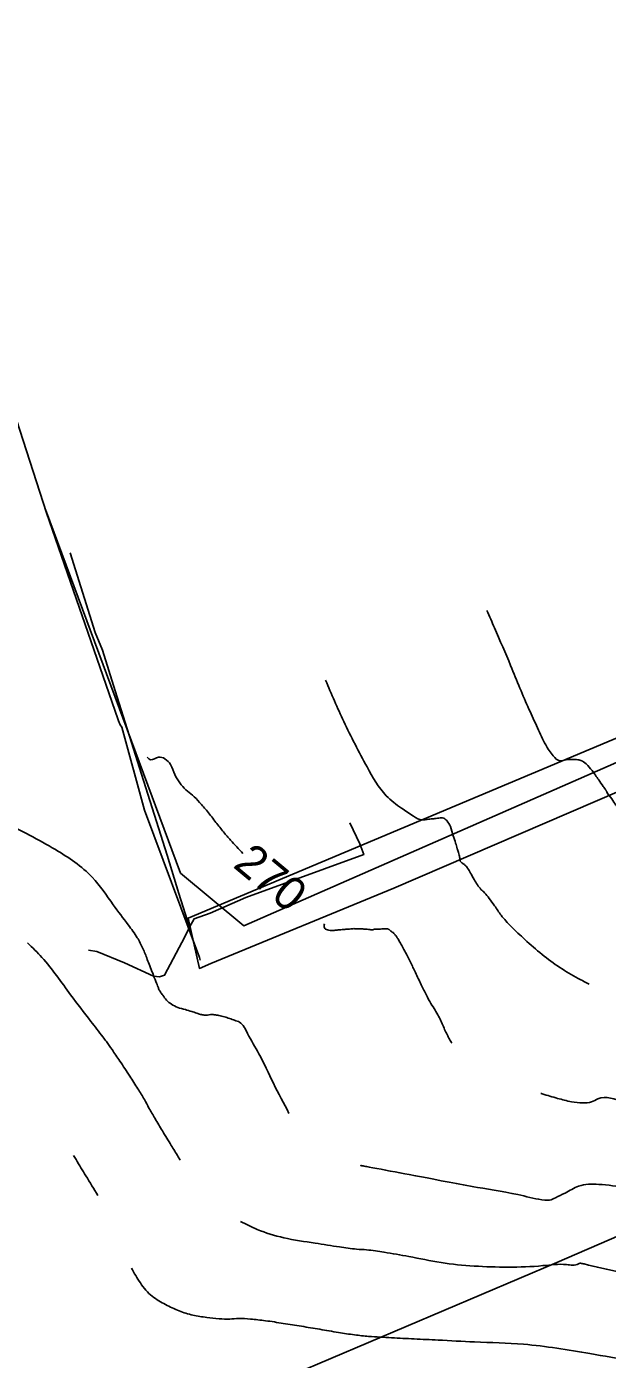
# Model space of a CAD drawing. Extents: x -478464 to -472469, y -1120963 to -1113785.
# Drawn here: x -475785 to -475715, y -1117032.4 to -1116871.8 of the extents above; entities that cross this region are included whole.
import ezdxf

# ---------------------------------------------------------------- set-up
doc = ezdxf.new("R2010")
doc.units = 0
for name, color, linetype in [('ObPÚ', 7, 'Continuous'), ('telekomunikační kabel_O2', 7, 'Continuous'), ('VAK_vodovod', 7, 'Continuous'), ('Vrstevnice_hlavni', 7, 'Continuous'), ('Vrstevnice_popis', 7, 'Continuous'), ('Vrstevnice_vedlejsi', 7, 'Continuous')]:
    doc.layers.add(name, color=color, linetype=linetype)

msp = doc.modelspace()

# ---------------------------------------------------------------- linework, layer by layer
at = {"layer": 'ObPÚ'}
msp.add_lwpolyline([(-475582.38, -1116858.98), (-475609.93, -1116877.62), (-475644, -1116900.2), (-475634.09, -1116923.52), (-475698.19, -1116950.87), (-475765.52, -1116979.2), (-475764.15, -1116985.27), (-475762.77, -1116984.68), (-475740.75, -1116975.6), (-475704.37, -1116959.91), (-475684.75, -1117004.96), (-475721.12, -1117020.7), (-475752.88, -1117034.21), (-475749.21, -1117050.03), (-475744.47, -1117062.49), (-475748.91, -1117064.2), (-475744.85, -1117076.56), (-475754.59, -1117081.64), (-475740.69, -1117110.42), (-475761.49, -1117122.43), (-475769.31, -1117126.94), (-475775.61, -1117130.12), (-475776.93, -1117131.38), (-475801.94, -1117143.82)], dxfattribs=at)
at = {"layer": 'telekomunikační kabel_O2'}
for points in [[(-475779.72, -1116935.16), (-475776.72, -1116944.8), (-475775.82, -1116946.89)], [(-475775.82, -1116946.89), (-475774.3, -1116951.81), (-475771.12, -1116961.84), (-475768.06, -1116971.62), (-475766.62, -1116976.22), (-475765.34, -1116980.29)], [(-475765.34, -1116980.29), (-475764.8, -1116979.28), (-475762.86, -1116978.62), (-475758.55, -1116976.73), (-475744.37, -1116971.54), (-475744.83, -1116970.26), (-475746.06, -1116967.73)], [(-475765.34, -1116980.29), (-475765.92, -1116981.46), (-475768.35, -1116986.07), (-475768.98, -1116986.28), (-475769.68, -1116986.19), (-475773.18, -1116984.59), (-475776.5, -1116983.23), (-475777.53, -1116983.05)]]:
    msp.add_lwpolyline(points, dxfattribs=at)
at = {"layer": 'VAK_vodovod'}
for points in [[(-475764.07, -1116984.29), (-475764.159, -1116983.95), (-475770.76, -1116966.2), (-475773.519, -1116956.18), (-475773.699, -1116955.909), (-475773.909, -1116955.44), (-475773.98, -1116955.18), (-475782.599, -1116930.34), (-475789.389, -1116909.29), (-475792.36, -1116901.129), (-475795.449, -1116892.25), (-475795.679, -1116891.569), (-475801.449, -1116877.079), (-475803.873, -1116870.356), (-475810.739, -1116851.899), (-475813.889, -1116838.01), (-475814.349, -1116835.61), (-475816.44, -1116816.799), (-475816.731, -1116810.878)], [(-475782.684, -1116929.977), (-475766.44, -1116973.781), (-475758.82, -1116980.133), (-475703.189, -1116955.74)]]:
    msp.add_lwpolyline(points, dxfattribs=at)
at = {"layer": 'Vrstevnice_hlavni'}
for points in [[(-475770.444, -1116959.812), (-475770.027, -1116960.112), (-475769.102, -1116959.807), (-475768.308, -1116960.004), (-475767.648, -1116960.702), (-475767.119, -1116961.902), (-475766.503, -1116962.916), (-475765.799, -1116963.743), (-475765.007, -1116964.385), (-475764.139, -1116965.254), (-475763.195, -1116966.349), (-475762.174, -1116967.671), (-475761.246, -1116968.823), (-475760.408, -1116969.806), (-475758.917, -1116971.433)], [(-475752.155, -1116974.761), (-475752.278, -1116974.524), (-475752.331, -1116974.447), (-475752.377, -1116974.41), (-475752.415, -1116974.415), (-475752.45, -1116974.42), (-475752.482, -1116974.426), (-475752.541, -1116974.439)], [(-475749.112, -1116979.911), (-475749.084, -1116980.363), (-475748.966, -1116980.529), (-475748.744, -1116980.634), (-475748.419, -1116980.68), (-475748.159, -1116980.701), (-475747.966, -1116980.699), (-475747.84, -1116980.673), (-475747.554, -1116980.64), (-475747.109, -1116980.599), (-475746.506, -1116980.551), (-475746.066, -1116980.515), (-475745.792, -1116980.49), (-475745.682, -1116980.477), (-475745.442, -1116980.476), (-475745.072, -1116980.485), (-475744.572, -1116980.507), (-475744.144, -1116980.533), (-475743.788, -1116980.563), (-475743.504, -1116980.598), (-475743.314, -1116980.614), (-475743.221, -1116980.611), (-475743.223, -1116980.59), (-475743.216, -1116980.574), (-475743.201, -1116980.564), (-475743.178, -1116980.559), (-475742.98, -1116980.549), (-475742.607, -1116980.532), (-475742.059, -1116980.51), (-475741.674, -1116980.502), (-475741.452, -1116980.509), (-475741.392, -1116980.531), (-475741.34, -1116980.559), (-475741.298, -1116980.593), (-475741.264, -1116980.634), (-475741.175, -1116980.708), (-475741.032, -1116980.815), (-475740.833, -1116980.954), (-475740.632, -1116981.157), (-475740.429, -1116981.424), (-475740.222, -1116981.754), (-475739.954, -1116982.217), (-475739.622, -1116982.813), (-475739.228, -1116983.543), (-475738.734, -1116984.524), (-475738.14, -1116985.756), (-475737.446, -1116987.241), (-475736.821, -1116988.49), (-475736.265, -1116989.503), (-475735.779, -1116990.281), (-475735.354, -1116991.032), (-475734.993, -1116991.754), (-475734.695, -1116992.449), (-475734.397, -1116993.087), (-475734.1, -1116993.67), (-475733.804, -1116994.197), (-475733.754, -1116994.287)], [(-475723.019, -1117000.326), (-475722.854, -1117000.379), (-475721.016, -1117000.925), (-475719.348, -1117001.335), (-475717.982, -1117001.478), (-475716.917, -1117001.356), (-475716.153, -1117000.967), (-475713.042, -1117001.384), (-475707.582, -1117002.608), (-475699.774, -1117004.638), (-475693.246, -1117006.296), (-475687.998, -1117007.584), (-475684.03, -1117008.499), (-475680.792, -1117009.282), (-475678.284, -1117009.933), (-475676.506, -1117010.452), (-475672.106, -1117010.892), (-475665.083, -1117011.253)]]:
    msp.add_spline(points, degree=3, dxfattribs=at)
at = {"layer": 'Vrstevnice_vedlejsi'}
for points in [[(-475729.527, -1116942.126), (-475728.611, -1116944.232), (-475726.669, -1116948.766), (-475725.544, -1116951.506), (-475724.466, -1116954.013), (-475723.434, -1116956.285), (-475722.449, -1116958.323), (-475721.548, -1116959.642), (-475720.729, -1116960.242), (-475719.994, -1116960.123), (-475719.328, -1116960.075), (-475718.731, -1116960.097), (-475718.204, -1116960.189), (-475717.583, -1116960.628), (-475716.868, -1116961.415), (-475716.061, -1116962.548), (-475715.508, -1116963.328), (-475715.21, -1116963.755), (-475715.167, -1116963.828), (-475715.132, -1116963.894), (-475715.104, -1116963.952), (-475715.085, -1116964.003), (-475714.792, -1116964.431), (-475714.224, -1116965.237), (-475713.382, -1116966.419), (-475712.234, -1116967.726), (-475710.782, -1116969.156), (-475709.024, -1116970.711), (-475706.212, -1116972.209), (-475702.344, -1116973.649), (-475697.421, -1116975.031), (-475692.698, -1116976.716), (-475688.176, -1116978.703), (-475683.853, -1116980.992), (-475678.496, -1116982.63), (-475672.102, -1116983.615), (-475664.674, -1116983.949), (-475657.807, -1116984.398), (-475651.502, -1116984.961), (-475645.759, -1116985.639), (-475640.754, -1116986.347), (-475636.487, -1116987.086), (-475632.96, -1116987.855), (-475627.187, -1116988.328), (-475619.17, -1116988.503), (-475608.909, -1116988.382), (-475599.585, -1116989.691), (-475591.198, -1116992.428), (-475583.75, -1116996.595), (-475579.328, -1117001.637), (-475577.932, -1117007.554), (-475579.563, -1117014.345), (-475580.658, -1117021.082), (-475581.217, -1117027.766), (-475581.24, -1117034.395), (-475582.353, -1117041.517), (-475584.557, -1117049.132), (-475587.852, -1117057.238), (-475590.037, -1117063.798), (-475591.112, -1117068.811)], [(-475717.205, -1116987.161), (-475718.526, -1116986.479), (-475720.741, -1116985.146), (-475722.885, -1116983.579), (-475724.958, -1116981.78), (-475726.601, -1116980.203), (-475727.814, -1116978.85), (-475728.597, -1116977.719), (-475729.263, -1116976.822), (-475729.811, -1116976.161), (-475730.242, -1116975.734), (-475730.666, -1116975.194), (-475731.082, -1116974.541), (-475731.491, -1116973.775), (-475731.855, -1116973.196), (-475732.174, -1116972.806), (-475732.448, -1116972.604), (-475732.637, -1116972.443), (-475732.741, -1116972.325), (-475732.761, -1116972.248), (-475732.78, -1116972.148), (-475732.799, -1116972.022), (-475732.818, -1116971.873), (-475732.873, -1116971.625), (-475732.966, -1116971.279), (-475733.095, -1116970.835), (-475733.299, -1116970.169), (-475733.575, -1116969.283), (-475733.925, -1116968.175), (-475734.359, -1116967.454), (-475734.877, -1116967.121), (-475735.478, -1116967.174), (-475736.089, -1116967.235), (-475736.708, -1116967.302), (-475737.336, -1116967.376), (-475738.368, -1116966.928), (-475739.805, -1116965.959), (-475741.646, -1116964.467), (-475743.969, -1116960.984), (-475746.775, -1116955.511), (-475748.963, -1116950.527)], [(-475788.03, -1116967.518), (-475787.795, -1116967.629), (-475781.498, -1116970.952), (-475777.078, -1116974.275), (-475774.537, -1116977.597), (-475772.727, -1116980.026), (-475771.647, -1116981.561), (-475771.297, -1116982.202), (-475770.979, -1116982.851), (-475770.692, -1116983.509), (-475770.437, -1116984.176), (-475770.136, -1116984.956), (-475769.79, -1116985.85), (-475769.398, -1116986.858), (-475769.136, -1116987.532), (-475769.004, -1116987.871), (-475769.002, -1116987.876), (-475769.001, -1116987.879), (-475769, -1116987.882), (-475768.999, -1116987.883), (-475768.999, -1116987.884), (-475768.998, -1116987.885), (-475768.852, -1116988.086), (-475768.561, -1116988.488), (-475768.125, -1116989.09), (-475767.529, -1116989.58), (-475766.772, -1116989.959), (-475765.856, -1116990.227), (-475765.092, -1116990.457), (-475764.483, -1116990.649), (-475764.027, -1116990.804), (-475763.601, -1116990.885), (-475763.205, -1116990.894), (-475762.84, -1116990.829), (-475762.377, -1116990.842), (-475761.816, -1116990.934), (-475761.157, -1116991.103), (-475760.523, -1116991.296), (-475759.914, -1116991.513), (-475759.331, -1116991.753), (-475758.359, -1116993.097), (-475756.997, -1116995.545), (-475755.247, -1116999.097), (-475753.369, -1117002.735)], [(-475784.856, -1116982.194), (-475783.127, -1116983.939), (-475779.673, -1116988.456), (-475777.228, -1116991.651), (-475775.793, -1116993.524), (-475775.368, -1116994.076), (-475774.686, -1116995.045), (-475773.746, -1116996.433), (-475772.548, -1116998.239), (-475771.564, -1116999.784), (-475770.793, -1117001.068), (-475770.234, -1117002.092), (-475769.508, -1117003.352), (-475768.615, -1117004.851), (-475767.555, -1117006.586), (-475766.714, -1117007.974), (-475766.472, -1117008.379)], [(-475779.319, -1117007.791), (-475779.013, -1117008.308), (-475777.842, -1117010.255), (-475776.381, -1117012.646)], [(-475743.816, -1117009.188), (-475744.435, -1117009.073), (-475738.882, -1117010.109), (-475730.644, -1117011.656), (-475725.08, -1117012.685), (-475722.191, -1117013.195), (-475721.975, -1117013.186), (-475721.285, -1117012.901), (-475720.12, -1117012.341), (-475718.481, -1117011.506), (-475716.047, -1117011.297), (-475712.82, -1117011.716), (-475708.798, -1117012.762), (-475703.378, -1117014.091), (-475696.56, -1117015.703), (-475688.344, -1117017.599), (-475681.639, -1117019.22), (-475676.446, -1117020.568), (-475672.765, -1117021.642), (-475668.29, -1117022.417), (-475663.022, -1117022.893), (-475656.96, -1117023.071), (-475651.811, -1117023.298), (-475647.576, -1117023.576), (-475644.255, -1117023.903), (-475641.565, -1117024.203), (-475639.507, -1117024.475)], [(-475759.201, -1117015.759), (-475757.199, -1117016.713), (-475754.002, -1117017.726), (-475750.213, -1117018.376), (-475747.285, -1117018.835), (-475745.221, -1117019.101), (-475744.019, -1117019.176), (-475741.924, -1117019.469), (-475738.937, -1117019.98), (-475735.058, -1117020.709), (-475731.072, -1117021.136), (-475726.979, -1117021.262), (-475722.779, -1117021.086), (-475719.947, -1117020.952), (-475718.483, -1117020.861), (-475718.388, -1117020.812), (-475718.246, -1117020.8), (-475718.057, -1117020.824)], [(-475772.354, -1117021.377), (-475771.276, -1117023.17), (-475769.834, -1117024.783), (-475768.231, -1117025.776), (-475766.603, -1117026.531), (-475764.949, -1117027.045), (-475763.271, -1117027.321), (-475761.793, -1117027.482), (-475760.515, -1117027.529), (-475759.438, -1117027.461), (-475758.002, -1117027.525), (-475756.207, -1117027.72), (-475754.053, -1117028.047), (-475751.871, -1117028.392), (-475749.659, -1117028.757), (-475747.418, -1117029.142), (-475745.46, -1117029.427), (-475743.784, -1117029.613), (-475742.391, -1117029.7), (-475741.011, -1117029.78), (-475739.643, -1117029.852), (-475738.287, -1117029.917), (-475735.414, -1117030.058), (-475731.023, -1117030.274), (-475725.114, -1117030.565), (-475717.13, -1117031.674), (-475707.07, -1117033.601), (-475694.935, -1117036.346), (-475686.642, -1117038.257), (-475682.19, -1117039.335), (-475681.58, -1117039.579), (-475681.049, -1117039.764), (-475680.598, -1117039.89), (-475680.225, -1117039.958), (-475678.419, -1117040.527), (-475675.18, -1117041.598), (-475670.508, -1117043.17), (-475666.913, -1117044.555), (-475664.396, -1117045.752), (-475662.956, -1117046.762), (-475660.81, -1117047.322), (-475657.96, -1117047.433), (-475654.404, -1117047.095), (-475653.011, -1117047.971), (-475653.781, -1117050.062)], [(-475718.057, -1117020.824), (-475717.822, -1117020.885), (-475713.511, -1117021.885), (-475705.123, -1117023.822), (-475692.658, -1117026.698), (-475682.487, -1117029.159), (-475674.608, -1117031.203), (-475669.024, -1117032.832), (-475664.474, -1117033.942), (-475660.96, -1117034.534), (-475658.481, -1117034.606), (-475655.268, -1117034.809), (-475651.321, -1117035.141), (-475646.64, -1117035.602), (-475643.466, -1117035.913), (-475641.798, -1117036.072), (-475641.636, -1117036.08), (-475641.467, -1117036.098), (-475641.291, -1117036.126), (-475641.109, -1117036.165), (-475640.524, -1117036.276), (-475639.535, -1117036.459), (-475638.143, -1117036.714), (-475637.057, -1117036.968), (-475636.277, -1117037.221), (-475635.804, -1117037.473), (-475635.337, -1117038.326), (-475634.876, -1117039.779), (-475634.42, -1117041.834), (-475634.07, -1117043.841), (-475633.824, -1117045.8), (-475633.682, -1117047.712), (-475634.619, -1117050.877), (-475636.636, -1117055.295), (-475639.731, -1117060.966), (-475642.222, -1117065.228), (-475644.109, -1117068.081), (-475645.391, -1117069.527), (-475647.093, -1117071.483), (-475649.216, -1117073.95), (-475651.759, -1117076.929), (-475655.228, -1117080.029), (-475659.623, -1117083.25), (-475664.945, -1117086.593), (-475669.489, -1117089.778), (-475673.256, -1117092.806), (-475676.246, -1117095.676), (-475679.672, -1117098.958), (-475683.535, -1117102.65), (-475687.834, -1117106.754), (-475691.789, -1117110.718), (-475695.399, -1117114.541), (-475698.664, -1117118.224), (-475701.2, -1117123.502), (-475703.006, -1117130.375), (-475704.082, -1117138.844), (-475704.473, -1117146.024), (-475704.178, -1117151.915), (-475703.197, -1117156.518), (-475700.122, -1117161.772), (-475694.953, -1117167.678), (-475687.69, -1117174.234), (-475681.519, -1117179.45), (-475676.442, -1117183.325), (-475672.457, -1117185.859), (-475668.214, -1117187.858), (-475663.714, -1117189.322), (-475658.957, -1117190.252), (-475655.221, -1117190.922), (-475652.506, -1117191.334), (-475650.814, -1117191.487), (-475648.971, -1117191.751), (-475646.979, -1117192.125), (-475644.837, -1117192.611), (-475643.325, -1117192.922), (-475642.443, -1117193.058), (-475642.191, -1117193.02), (-475641.928, -1117192.99), (-475641.653, -1117192.968), (-475641.366, -1117192.955), (-475640.859, -1117192.915), (-475640.132, -1117192.848), (-475639.184, -1117192.754), (-475638.197, -1117192.847), (-475637.169, -1117193.129), (-475636.101, -1117193.598), (-475635.255, -1117193.9), (-475634.632, -1117194.036), (-475634.231, -1117194.006), (-475632.792, -1117193.698), (-475630.315, -1117193.112), (-475626.801, -1117192.25), (-475624.352, -1117191.644), (-475622.968, -1117191.295), (-475622.65, -1117191.203), (-475622.328, -1117191.121), (-475622, -1117191.049)]]:
    msp.add_spline(points, degree=3, dxfattribs=at)

# ---------------------------------------------------------------- texts
at = {"layer": 'Vrstevnice_popis'}
msp.add_text(' 270 ', height=4, rotation=320.18645, dxfattribs=at).set_placement((-475761.384, -1116972.015))

doc.saveas('drawing.dxf')
